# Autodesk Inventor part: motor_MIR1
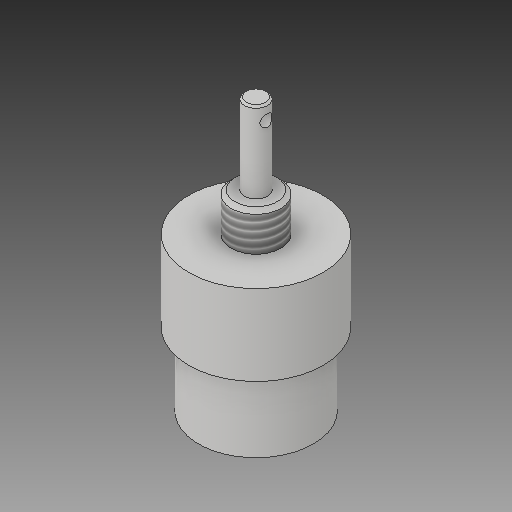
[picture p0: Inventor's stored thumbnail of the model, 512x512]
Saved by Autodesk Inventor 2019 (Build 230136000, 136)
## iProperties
Created: 2019-10
Part Number: motor_MIR1
Material: Generic
Document SubType Name: Modeling
Designer: PRADYUMNA
Density: 1 g/cm^3
Appearance: Default
Author: Asus
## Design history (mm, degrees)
derived "motor.ipt"
  sketch "Sketch1"
    geometry: C1 r 6.5 at (0, 0) reference; 1 further point
  sketch "Sketch2"
    geometry: 1 further point
  sketch "Sketch3"
    geometry: C1 r 17.5 at (0, 0) reference; 1 further point
  sketch "Sketch4"
    geometry: C1 r 15 at (0, 0) reference; 1 further point
  sketch "Sketch5"
    geometry: C1 r 3 at (0, 0) reference; 1 further point
  sketch "Sketch6"
    geometry: C1 r 1.55 at (-27.143, 0) reference; 1 further point
  sketch "Sketch7"
    geometry: L1 (-12.192, 2.12)-(-11.485, 2.12) reference; L2 (-11.485, 2.12)-(-11.485, -2.356) reference; L3 (-11.485, -2.356)-(-12.192, -2.356) reference; L4 (-12.192, -2.356)-(-12.192, 2.12) reference; L5 (11.603, 2.12)-(12.546, 2.12) reference; L6 (12.546, 2.12)-(12.546, -2.356) reference; L7 (12.546, -2.356)-(11.603, -2.356) reference; L8 (11.603, -2.356)-(11.603, 2.12) reference; 1 further point
feature "Solid1::motor.ipt"
tag "TaggingFeature1"
body "Solid1"
